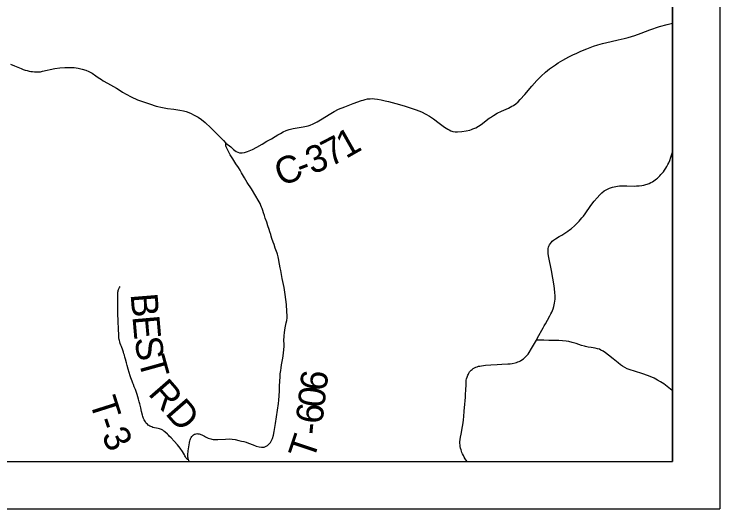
# Model space of a CAD drawing. Extents: x -10 to 158, y 8 to 33.
# Drawn here: x 131.514 to 133.004, y 24.962 to 26.006 of the extents above; entities that cross this region are included whole.
import ezdxf

# ---------------------------------------------------------------- set-up
doc = ezdxf.new("R2010")
doc.units = 0
for name, color, linetype in [('GM_X_County_Road', 7, 'Continuous'), ('GM_X_County_Road_Text', 7, 'Continuous'), ('GM_X_Township_Road', 7, 'Continuous'), ('GM_X_Township_Road_Text', 7, 'Continuous'), ('GM_X_Township_Text', 7, 'Continuous'), ('SH_Data', 7, 'Continuous')]:
    doc.layers.add(name, color=color, linetype=linetype)

msp = doc.modelspace()

# ---------------------------------------------------------------- linework, layer by layer
at = {"layer": 'GM_X_County_Road'}
for points in [[(132.6506, 25.8944), (132.6569, 25.8988), (132.6624, 25.9025), (132.6674, 25.9055), (132.6724, 25.9084), (132.6788, 25.912), (132.6851, 25.9153), (132.6932, 25.9194), (132.702, 25.9235), (132.7102, 25.9272), (132.7228, 25.9325), (132.7367, 25.9379), (132.7461, 25.9411), (132.7563, 25.9439), (132.7744, 25.948), (132.789, 25.951), (132.8015, 25.9538), (132.8105, 25.9562), (132.824, 25.9605), (132.8374, 25.9654), (132.856, 25.9722), (132.8767, 25.9791), (132.8928, 25.9839), (132.9038, 25.9865)], [(131.5062, 25.9), (131.515, 25.8965), (131.5287, 25.8907), (131.5329, 25.8888), (131.5374, 25.8877), (131.5418, 25.8865), (131.5457, 25.8855), (131.5491, 25.8849), (131.553, 25.8843), (131.5569, 25.8841), (131.5612, 25.8838), (131.5658, 25.8838), (131.5699, 25.8842), (131.5737, 25.8852), (131.5999, 25.8906), (131.6104, 25.8921), (131.621, 25.893), (131.631, 25.8932), (131.6404, 25.8927), (131.6491, 25.8915), (131.6576, 25.8895), (131.6654, 25.8871), (131.6718, 25.8844), (131.6784, 25.8808), (131.6861, 25.8756), (131.6917, 25.8719), (131.6984, 25.8675), (131.702, 25.8651), (131.711, 25.86), (131.7235, 25.8529), (131.73, 25.8491), (131.7359, 25.8456), (131.743, 25.8413), (131.7502, 25.8369), (131.7611, 25.8311), (131.7746, 25.8249), (131.7827, 25.8218), (131.7997, 25.8161), (131.8139, 25.8118), (131.8272, 25.8086), (131.8375, 25.8066), (131.851, 25.8048), (131.864, 25.8031), (131.8713, 25.8017), (131.8774, 25.7999), (131.8861, 25.7965), (131.8941, 25.7928), (131.9022, 25.7881), (131.9094, 25.7831), (131.9172, 25.7768), (131.9291, 25.7659), (131.9562, 25.7394), (131.9612, 25.7337)], [(132.5194, 25.7875), (132.5258, 25.7918), (132.5338, 25.7964), (132.5426, 25.8008), (132.5577, 25.8076), (132.5648, 25.8113), (132.5682, 25.8132), (132.5733, 25.8167), (132.5782, 25.8208), (132.5825, 25.8253), (132.5924, 25.8363), (132.6068, 25.8534), (132.6174, 25.8657), (132.6266, 25.875), (132.6359, 25.8833), (132.6442, 25.8899), (132.6506, 25.8944)], [(131.9612, 25.7337), (131.9711, 25.7255), (131.977, 25.7202), (131.98, 25.7179), (131.9829, 25.7161), (131.9859, 25.7146), (131.9897, 25.7134), (131.9925, 25.7129), (131.9956, 25.7131), (132.0003, 25.7139), (132.0067, 25.716), (132.0169, 25.7204), (132.0263, 25.725), (132.0373, 25.7315), (132.0475, 25.7374), (132.057, 25.7427), (132.065, 25.7475), (132.0706, 25.7508), (132.0761, 25.7541), (132.0816, 25.7571), (132.0884, 25.7601), (132.0944, 25.7621), (132.103, 25.7642), (132.1244, 25.7676), (132.131, 25.7691), (132.1347, 25.7701), (132.1386, 25.7715), (132.1454, 25.7744), (132.1536, 25.7786), (132.1643, 25.7849), (132.179, 25.7942), (132.1893, 25.8001), (132.1988, 25.8048), (132.212, 25.8103), (132.2295, 25.8169), (132.2476, 25.8234), (132.2505, 25.8243), (132.2552, 25.8257), (132.2596, 25.8267), (132.2653, 25.8272), (132.2695, 25.8275), (132.2747, 25.8272), (132.2809, 25.8264), (132.2889, 25.8249), (132.2974, 25.8229), (132.3046, 25.8211), (132.3196, 25.817), (132.3375, 25.812), (132.35, 25.8082), (132.3629, 25.8037), (132.3739, 25.7992), (132.3829, 25.7948), (132.3911, 25.7902), (132.3994, 25.7846), (132.4114, 25.7757), (132.4228, 25.7673), (132.4295, 25.763), (132.4326, 25.7613), (132.436, 25.7597), (132.44, 25.7583), (132.4447, 25.7575), (132.4502, 25.7574), (132.4588, 25.758), (132.4685, 25.7595), (132.4757, 25.7612), (132.4794, 25.7624), (132.4826, 25.7635), (132.4883, 25.7659), (132.4942, 25.7692), (132.4998, 25.7729), (132.517, 25.7859), (132.5194, 25.7875)], [(132.6164, 25.3184), (132.6188, 25.3228), (132.6306, 25.344), (132.633, 25.3485), (132.6356, 25.3526), (132.6401, 25.3604), (132.6451, 25.3693), (132.6472, 25.3735), (132.6489, 25.377), (132.6504, 25.3803), (132.6517, 25.3839), (132.6533, 25.3891), (132.6549, 25.3963), (132.6558, 25.4043), (132.6561, 25.411), (132.6557, 25.4196), (132.6539, 25.4325), (132.6513, 25.449), (132.6482, 25.4649), (132.6424, 25.4923), (132.6417, 25.4962), (132.6412, 25.5011), (132.6411, 25.5055), (132.6411, 25.5081), (132.6416, 25.5112), (132.6423, 25.5139), (132.643, 25.5165), (132.6442, 25.519), (132.6462, 25.5222), (132.6481, 25.5248), (132.6501, 25.5269), (132.6524, 25.5286), (132.6545, 25.5301), (132.6565, 25.5315), (132.6646, 25.5364), (132.67, 25.5396), (132.683, 25.5478), (132.6865, 25.5504), (132.6899, 25.5531), (132.6978, 25.56), (132.702, 25.5639), (132.7065, 25.5688), (132.7126, 25.5757), (132.7158, 25.5796), (132.7194, 25.5845), (132.7317, 25.6017), (132.7386, 25.6113), (132.7446, 25.6185), (132.7501, 25.6245), (132.7547, 25.6288), (132.7596, 25.6327), (132.765, 25.636), (132.7707, 25.6388), (132.7773, 25.6409), (132.7806, 25.6417), (132.7841, 25.6424), (132.7876, 25.6429), (132.7922, 25.6432), (132.8072, 25.6432), (132.8233, 25.643), (132.8281, 25.6432), (132.8337, 25.6437), (132.8388, 25.6443), (132.8431, 25.6451), (132.8473, 25.6462), (132.8506, 25.6472), (132.8546, 25.6486), (132.8583, 25.6504), (132.8615, 25.6521), (132.8642, 25.654), (132.8669, 25.6558), (132.8697, 25.6579), (132.8721, 25.6598), (132.8747, 25.6624), (132.8772, 25.6647), (132.8794, 25.6673), (132.8847, 25.6733), (132.8872, 25.6768), (132.8898, 25.6809), (132.8919, 25.6845), (132.894, 25.6884), (132.8958, 25.6921), (132.8979, 25.6968), (132.9003, 25.7038), (132.9033, 25.7125), (132.9038, 25.7144)], [(132.4699, 25.0623), (132.4695, 25.0631), (132.4664, 25.0679), (132.4641, 25.0715), (132.4624, 25.0749), (132.4607, 25.0782), (132.4594, 25.0812), (132.4583, 25.0841), (132.4574, 25.0869), (132.4565, 25.0901), (132.4558, 25.0936), (132.4554, 25.097), (132.4552, 25.101), (132.4552, 25.1039), (132.4556, 25.1083), (132.4563, 25.1133), (132.4574, 25.1197), (132.4604, 25.1359), (132.4617, 25.1438), (132.4624, 25.1499), (132.4631, 25.1568), (132.4641, 25.1685), (132.4648, 25.1763), (132.4654, 25.1827), (132.4661, 25.1907), (132.4666, 25.1969), (132.4671, 25.2037), (132.4674, 25.2136), (132.4679, 25.2241), (132.4681, 25.2308), (132.4685, 25.234), (132.4692, 25.2367), (132.4703, 25.2402), (132.4719, 25.2441), (132.4729, 25.2465), (132.474, 25.2488), (132.4756, 25.2512), (132.4774, 25.2535), (132.479, 25.2551), (132.4807, 25.2565), (132.4833, 25.2584), (132.4857, 25.2597), (132.4884, 25.261), (132.4913, 25.2619), (132.4945, 25.2629), (132.4972, 25.2635), (132.5006, 25.2641), (132.5087, 25.2651), (132.5206, 25.266), (132.534, 25.2666), (132.5435, 25.2672), (132.5565, 25.2679), (132.5614, 25.2684), (132.5656, 25.2691), (132.5716, 25.2704), (132.5746, 25.2712), (132.5774, 25.2723), (132.5803, 25.2733), (132.5832, 25.2747), (132.5861, 25.2765), (132.5891, 25.2787), (132.5915, 25.2806), (132.5944, 25.2835), (132.5966, 25.2858), (132.5989, 25.2886), (132.6014, 25.2921), (132.6065, 25.3005), (132.6106, 25.3078), (132.6164, 25.3184)]]:
    msp.add_lwpolyline(points, dxfattribs=at)
at = {"layer": 'GM_X_Township_Road'}
for points in [[(131.8822, 25.0657), (131.8819, 25.0665), (131.8813, 25.0689), (131.8808, 25.0714), (131.8806, 25.0739), (131.8807, 25.0763), (131.8816, 25.0849), (131.8832, 25.0977), (131.884, 25.1017), (131.8843, 25.1037), (131.8848, 25.1054), (131.8854, 25.1076), (131.8861, 25.1098), (131.8868, 25.1113), (131.8876, 25.1131), (131.8889, 25.1149), (131.8902, 25.1165), (131.8926, 25.1185), (131.8947, 25.1196), (131.8963, 25.1202), (131.8982, 25.1207), (131.9, 25.121), (131.9019, 25.1209), (131.9034, 25.1206), (131.9048, 25.1203), (131.9064, 25.1198), (131.9083, 25.1191), (131.91, 25.1184), (131.9118, 25.1175), (131.9155, 25.1154), (131.9181, 25.1139), (131.9209, 25.1126), (131.9237, 25.1114), (131.9264, 25.1105), (131.9291, 25.1098), (131.9315, 25.1093), (131.9339, 25.1089), (131.9369, 25.1086), (131.9404, 25.1083), (131.9437, 25.1086), (131.9603, 25.1096), (131.9677, 25.1098), (131.9739, 25.1093), (131.9808, 25.1083), (131.9881, 25.1068), (131.994, 25.1054), (131.9988, 25.1042), (132.004, 25.1027), (132.0087, 25.1012), (132.0184, 25.0972), (132.0246, 25.0947), (132.0311, 25.093), (132.0359, 25.0922), (132.039, 25.0921), (132.042, 25.0927), (132.0448, 25.0938), (132.0485, 25.0962), (132.0523, 25.0994), (132.0551, 25.1026), (132.0575, 25.1063), (132.0595, 25.1108), (132.0614, 25.1174), (132.063, 25.1253), (132.0655, 25.1425), (132.0698, 25.1708), (132.0718, 25.1843), (132.0728, 25.1914), (132.0735, 25.201), (132.0744, 25.2113), (132.0745, 25.2221), (132.0754, 25.2407), (132.0759, 25.2474), (132.0767, 25.2543), (132.0774, 25.2598), (132.0785, 25.266), (132.0796, 25.2729), (132.0811, 25.28), (132.0828, 25.2904), (132.0836, 25.2984), (132.0838, 25.3046), (132.084, 25.3105), (132.0835, 25.317), (132.0838, 25.3275), (132.0845, 25.3343), (132.086, 25.3442), (132.0875, 25.3508), (132.0885, 25.3547), (132.0894, 25.3598), (132.0902, 25.3653), (132.0904, 25.3696), (132.0897, 25.3784), (132.0886, 25.3931), (132.0861, 25.4141), (132.0838, 25.4288), (132.0801, 25.4483), (132.0769, 25.4648), (132.0757, 25.4709), (132.0743, 25.4782), (132.072, 25.4903), (132.0711, 25.4938), (132.0705, 25.4966), (132.0697, 25.4995), (132.069, 25.5017), (132.0676, 25.5052), (132.0652, 25.5124), (132.0626, 25.5196), (132.061, 25.5246), (132.0581, 25.5327), (132.0567, 25.5374), (132.0556, 25.541), (132.054, 25.5463), (132.0526, 25.5511), (132.0498, 25.5593), (132.0471, 25.5669), (132.0441, 25.5754), (132.0423, 25.5809), (132.0407, 25.5863), (132.0393, 25.5913), (132.0379, 25.5955), (132.0365, 25.5986), (132.035, 25.6023), (132.0331, 25.6059), (132.0293, 25.613), (132.0243, 25.6216), (132.0149, 25.6369), (132.0062, 25.6505), (132.0001, 25.6607), (131.9942, 25.6706), (131.9911, 25.6763), (131.9873, 25.6824), (131.9823, 25.6902), (131.9754, 25.7005), (131.9701, 25.7089), (131.9663, 25.7159), (131.963, 25.7227), (131.9617, 25.7259), (131.961, 25.7278), (131.9607, 25.7297), (131.9608, 25.7319), (131.9612, 25.7337)], [(131.8822, 25.0657), (131.8803, 25.0666), (131.8791, 25.0674), (131.8782, 25.0681), (131.8772, 25.0694), (131.8764, 25.0706), (131.8755, 25.0723), (131.8746, 25.0741), (131.8735, 25.0763), (131.8695, 25.0833), (131.8647, 25.0905), (131.8591, 25.0971), (131.852, 25.1048), (131.8452, 25.1119), (131.8414, 25.1158), (131.8395, 25.1178), (131.8376, 25.1198), (131.8321, 25.1248), (131.8301, 25.1265), (131.8276, 25.1281), (131.8253, 25.1295), (131.8228, 25.1307), (131.8205, 25.1314), (131.8179, 25.132), (131.807, 25.1342), (131.8046, 25.135), (131.8023, 25.1357), (131.8004, 25.1366), (131.7985, 25.1379), (131.7968, 25.139), (131.7952, 25.1406), (131.7936, 25.1423), (131.7923, 25.1438), (131.791, 25.1457), (131.7897, 25.1478), (131.7884, 25.1503), (131.7872, 25.1531), (131.786, 25.1568), (131.7852, 25.1596), (131.7831, 25.1674), (131.7813, 25.1753), (131.7791, 25.1836), (131.7778, 25.1883), (131.7763, 25.1937), (131.7751, 25.1983), (131.7734, 25.2038), (131.772, 25.208), (131.7701, 25.2137), (131.7676, 25.2196), (131.7658, 25.2243), (131.7645, 25.2277), (131.7629, 25.2314), (131.7601, 25.2387), (131.7586, 25.2429), (131.7567, 25.2498), (131.7546, 25.2569), (131.7527, 25.2644), (131.7511, 25.2706), (131.7493, 25.2781), (131.748, 25.2822), (131.7468, 25.2861), (131.7458, 25.2891), (131.7446, 25.2926), (131.7431, 25.2967), (131.7404, 25.3045), (131.7392, 25.3077), (131.7381, 25.311), (131.7371, 25.3146), (131.7363, 25.3171), (131.7357, 25.3195), (131.7352, 25.3233), (131.7349, 25.3279), (131.7342, 25.3427), (131.7338, 25.3564), (131.7332, 25.3756), (131.7329, 25.3943), (131.7328, 25.4079), (131.7329, 25.4163), (131.733, 25.4194), (131.7333, 25.4212), (131.7336, 25.423), (131.7343, 25.4247), (131.735, 25.4264), (131.7364, 25.4289), (131.7376, 25.4313)], [(132.9038, 25.2112), (132.9029, 25.2119), (132.8928, 25.2202), (132.8854, 25.2258), (132.8787, 25.2303), (132.8722, 25.234), (132.865, 25.2377), (132.8599, 25.2399), (132.8507, 25.2436), (132.8413, 25.2468), (132.8235, 25.2524), (132.8147, 25.2554), (132.8084, 25.2579), (132.8033, 25.2604), (132.7985, 25.2631), (132.7943, 25.2659), (132.7889, 25.27), (132.7783, 25.2787), (132.7687, 25.2865), (132.7623, 25.2914), (132.7571, 25.2949), (132.7528, 25.2973), (132.7494, 25.2988), (132.7452, 25.3001), (132.7404, 25.3012), (132.7318, 25.3025), (132.7257, 25.3035), (132.7232, 25.304), (132.7202, 25.3047), (132.7178, 25.3054), (132.7118, 25.3069), (132.7006, 25.3107), (132.6923, 25.3133), (132.6851, 25.3151), (132.679, 25.3161), (132.6716, 25.3169), (132.6641, 25.3173), (132.6517, 25.3175), (132.643, 25.3175), (132.6324, 25.3178), (132.6233, 25.3182), (132.6164, 25.3184)], [(131.8834, 25.0623), (131.8826, 25.0643), (131.8822, 25.0657)]]:
    msp.add_lwpolyline(points, dxfattribs=at)
at = {"layer": 'GM_X_Township_Text'}
msp.add_lwpolyline([(130.461, 27.8534), (130.4499, 27.7117), (130.4527, 27.3822), (130.46, 27.1989), (130.4491, 26.3467), (130.4362, 25.0623), (132.9038, 25.0623), (132.9038, 27.8123)], dxfattribs=at)
at = {"layer": 'SH_Data'}
for p, q in [((133.0038, 31.9623), (133.0038, 24.9623)), ((132.9038, 31.8623), (132.9038, 25.0623)), ((126.1038, 25.0623), (132.9038, 25.0623)), ((126.0038, 24.9623), (133.0038, 24.9623))]:
    msp.add_line(p, q, dxfattribs=at)

# ---------------------------------------------------------------- texts
at = {"layer": 'GM_X_County_Road_Text'}
for s, rotation, p in [('1', 29.5196, (132.2143, 25.6998)), ('7', 27.4691, (132.1813, 25.6826)), ('3', 21.4703, (132.1428, 25.6671)), ('C', 21.0092, (132.077, 25.6418)), ('-', 21.0715, (132.1206, 25.6586))]:
    msp.add_text(s, height=0.0568, rotation=rotation, dxfattribs=at).set_placement(p)
at = {"layer": 'GM_X_Township_Road_Text'}
for s, height, rotation, p in [('B', 0.0568, 274.7319, (131.7597, 25.415)), ('E', 0.0568, 274.976, (131.7636, 25.3682)), ('S', 0.0568, 279.031, (131.7678, 25.3215)), ('T', 0.0568, 285.5435, (131.7753, 25.2768)), ('6', 0.0568, 82.9577, (132.1728, 25.2091)), ('RD', 0.05682, 311.0922, (131.7951, 25.2045)), ('0', 0.0568, 82.9438, (132.1685, 25.1743)), ('T', 0.0568, 287.5974, (131.6726, 25.1892)), ('6', 0.0568, 82.8517, (132.1642, 25.1395)), ('-', 0.0568, 288.0595, (131.6856, 25.1483)), ('3', 0.0568, 298.0327, (131.697, 25.1162)), ('-', 0.0568, 84.5179, (132.162, 25.1167)), ('T', 0.0568, 71.5325, (132.1456, 25.0627))]:
    msp.add_text(s, height=height, rotation=rotation, dxfattribs=at).set_placement(p)

doc.saveas('drawing.dxf')
